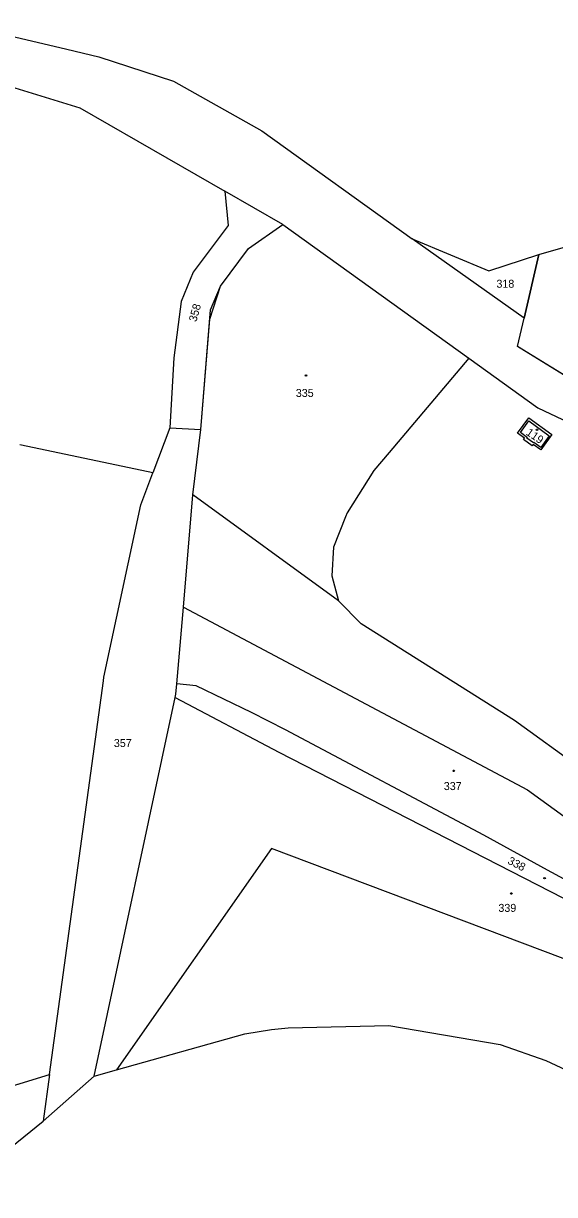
# Model space of a CAD drawing. Extents: x -841286 to -834997, y -1020681 to -1017810.
# Drawn here: x -836086.8 to -835974.1, y -1019708.5 to -1019459.7 of the extents above; entities that cross this region are included whole.
import ezdxf

# ---------------------------------------------------------------- set-up
doc = ezdxf.new("R2010")
doc.units = 0
for name, color, linetype in [('OVNE_POP', 7, 'Continuous'), ('OVNE_PRE', 7, 'Continuous'), ('OVNE_SET', 7, 'Continuous'), ('OVNI_PRE', 7, 'Continuous'), ('OVNI_SET', 7, 'Continuous')]:
    doc.layers.add(name, color=color, linetype=linetype)

msp = doc.modelspace()

# ---------------------------------------------------------------- linework, layer by layer
at = {"layer": 'OVNE_POP'}
for points in [[(-836026.74, -1019534.34), (-836026.65, -1019534.49), (-836026.74, -1019534.64), (-836026.92, -1019534.64), (-836027.01, -1019534.49), (-836026.92, -1019534.34)], [(-835995.38, -1019618.36), (-835995.29, -1019618.51), (-835995.38, -1019618.66), (-835995.56, -1019618.66), (-835995.65, -1019618.51), (-835995.56, -1019618.36)], [(-835976.04, -1019641.21), (-835976.03, -1019641.38), (-835976.18, -1019641.47), (-835976.34, -1019641.39), (-835976.35, -1019641.22), (-835976.2, -1019641.13)], [(-835983.15, -1019644.41), (-835983.06, -1019644.56), (-835983.15, -1019644.71), (-835983.33, -1019644.71), (-835983.42, -1019644.56), (-835983.33, -1019644.41)]]:
    msp.add_lwpolyline(points, close=True, dxfattribs=at)
at = {"layer": 'OVNE_SET'}
for p, q in [((-836100.7, -1019459.72), (-836077.61, -1019465.18)), ((-836077.61, -1019465.18), (-836070.81, -1019466.85)), ((-836102.74, -1019469.13), (-836074.81, -1019477.66)), ((-836070.81, -1019466.85), (-836054.99, -1019471.99)), ((-836054.99, -1019471.99), (-836036.21, -1019482.56)), ((-836074.81, -1019477.66), (-836044.05, -1019495.33)), ((-836036.21, -1019482.56), (-836004.29, -1019505.46)), ((-835977.44, -1019508.81), (-835896.74, -1019485.76)), ((-836044.05, -1019495.33), (-836043.36, -1019502.68)), ((-836031.74, -1019502.43), (-836044.05, -1019495.33)), ((-836043.36, -1019502.68), (-836050.77, -1019512.55)), ((-836039.02, -1019507.52), (-836031.74, -1019502.43)), ((-836031.74, -1019502.43), (-835992.24, -1019530.86)), ((-836004.29, -1019505.46), (-835988.02, -1019512.3)), ((-835980.55, -1019522.3), (-836004.29, -1019505.46)), ((-836044.98, -1019515.5), (-836039.02, -1019507.52)), ((-835988.02, -1019512.3), (-835977.44, -1019508.81)), ((-835977.44, -1019508.81), (-835980.55, -1019522.3)), ((-836050.77, -1019512.55), (-836053.34, -1019518.8)), ((-836047.08, -1019520.56), (-836044.98, -1019515.5)), ((-836053.34, -1019518.8), (-836054.91, -1019530.79)), ((-836049.17, -1019545.96), (-836047.08, -1019520.56)), ((-835981.95, -1019528.35), (-835980.55, -1019522.3)), ((-835964.53, -1019539.07), (-835981.95, -1019528.35)), ((-836054.91, -1019530.79), (-836055.71, -1019545.6)), ((-835992.24, -1019530.86), (-836009.2, -1019550.87)), ((-835992.24, -1019530.86), (-835977.64, -1019541.38)), ((-835977.64, -1019541.38), (-835967.33, -1019546.31)), ((-836055.71, -1019545.6), (-836059.34, -1019555.19)), ((-836055.71, -1019545.6), (-836049.17, -1019545.96)), ((-836050.88, -1019559.87), (-836049.17, -1019545.96)), ((-836069.74, -1019553), (-836087.56, -1019549.25)), ((-836009.2, -1019550.87), (-836012.43, -1019554.69)), ((-836059.34, -1019555.19), (-836069.74, -1019553)), ((-836061.92, -1019562), (-836059.34, -1019555.19)), ((-836012.43, -1019554.69), (-836018.11, -1019563.68)), ((-836052.87, -1019583.71), (-836050.88, -1019559.87)), ((-836019.93, -1019582.35), (-836050.88, -1019559.87)), ((-836069.72, -1019598.62), (-836061.92, -1019562)), ((-836018.11, -1019563.68), (-836018.44, -1019564.54)), ((-836018.44, -1019564.54), (-836020.97, -1019571.01)), ((-836020.97, -1019571.01), (-836021.37, -1019577.04)), ((-836021.37, -1019577.04), (-836019.93, -1019582.35)), ((-836054.22, -1019599.98), (-836052.87, -1019583.71)), ((-836052.87, -1019583.71), (-835979.84, -1019622.54)), ((-836015.16, -1019587.27), (-836019.93, -1019582.35)), ((-835982.57, -1019607.79), (-836015.16, -1019587.27)), ((-836069.85, -1019599.4), (-836069.72, -1019598.62)), ((-836081.27, -1019683), (-836069.85, -1019599.4)), ((-836054.46, -1019602.21), (-836054.22, -1019599.98)), ((-836050.17, -1019600.42), (-836054.22, -1019599.98)), ((-836038.41, -1019606.13), (-836050.17, -1019600.42)), ((-836071.78, -1019683.33), (-836054.58, -1019602.94)), ((-836054.58, -1019602.94), (-836054.46, -1019602.21)), ((-836054.58, -1019602.94), (-836032.59, -1019614.53)), ((-836031.18, -1019609.8), (-836038.41, -1019606.13)), ((-835968.17, -1019618.29), (-835982.57, -1019607.79)), ((-835989.09, -1019632.18), (-836031.18, -1019609.8)), ((-836032.59, -1019614.53), (-835969.54, -1019646.89)), ((-835979.84, -1019622.54), (-835903.29, -1019678.02)), ((-835975.56, -1019639.57), (-835989.09, -1019632.18)), ((-836034.19, -1019634.96), (-836067.09, -1019682.01)), ((-835937.02, -1019671.68), (-836034.19, -1019634.96)), ((-835950.97, -1019653.1), (-835975.56, -1019639.57)), ((-836034.17, -1019673.46), (-836030.61, -1019673.1)), ((-836030.61, -1019673.1), (-836009.27, -1019672.61)), ((-836009.27, -1019672.61), (-835985.65, -1019676.6)), ((-836067.09, -1019682.01), (-836039.82, -1019674.35)), ((-836039.82, -1019674.35), (-836034.17, -1019673.46)), ((-835985.65, -1019676.6), (-835975.95, -1019680.01)), ((-835975.95, -1019680.01), (-835960.3, -1019687.33)), ((-836100.96, -1019689.05), (-836081.27, -1019683)), ((-836081.27, -1019683), (-836082.63, -1019692.89)), ((-836071.78, -1019683.33), (-836067.09, -1019682.01)), ((-836082.63, -1019692.89), (-836071.78, -1019683.33)), ((-836101.96, -1019708.51), (-836082.63, -1019692.89))]:
    msp.add_line(p, q, dxfattribs=at)
msp.add_lwpolyline([(-835979.54, -1019543.53), (-835974.63, -1019547.05), (-835976.97, -1019550.33), (-835978.61, -1019549.15), (-835978.82, -1019549.46), (-835980.64, -1019548.13), (-835980.45, -1019547.83), (-835981.92, -1019546.74), (-835979.54, -1019543.53)], dxfattribs=at)
at = {"layer": 'OVNI_PRE'}
msp.add_lwpolyline([(-835977.71, -1019545.9), (-835977.62, -1019546.05), (-835977.71, -1019546.2), (-835977.89, -1019546.2), (-835977.98, -1019546.05), (-835977.89, -1019545.9)], close=True, dxfattribs=at)
at = {"layer": 'OVNI_SET'}
for points in [[(-835964.53, -1019539.07), (-835981.95, -1019528.35), (-835980.55, -1019522.3), (-835977.44, -1019508.81), (-835896.74, -1019485.7)], [(-836100.96, -1019689.05), (-836081.27, -1019683), (-836082.63, -1019692.89), (-836071.78, -1019683.33), (-836054.58, -1019602.94), (-836054.46, -1019602.21), (-836054.22, -1019599.98), (-836052.87, -1019583.71), (-836050.88, -1019559.87), (-836049.17, -1019545.96), (-836047.24, -1019522.54), (-836044.98, -1019515.5), (-836039.02, -1019507.52), (-836031.74, -1019502.43), (-836044.05, -1019495.33), (-836043.36, -1019502.68), (-836050.77, -1019512.55), (-836053.34, -1019518.8), (-836054.91, -1019530.79), (-836055.71, -1019545.6), (-836059.34, -1019555.19), (-836069.74, -1019553), (-836087.56, -1019549.25)], [(-835979.55, -1019544.17), (-835975.22, -1019547.3), (-835977.01, -1019549.8), (-835978.48, -1019548.73), (-835978.57, -1019548.85), (-835979.94, -1019547.85), (-835979.85, -1019547.73), (-835981.33, -1019546.65), (-835979.55, -1019544.17)]]:
    msp.add_lwpolyline(points, dxfattribs=at)

# ---------------------------------------------------------------- texts
at = {"layer": 'OVNE_PRE'}
for s, p in [('318', (-835986.42, -1019515.87)), ('335', (-836029, -1019539.07)), ('357', (-836067.62, -1019613.44)), ('337', (-835997.59, -1019622.58)), ('339', (-835986, -1019648.46))]:
    msp.add_text(s, height=1.7, dxfattribs=at).set_placement(p)
for s, rotation, p in [('358', 74.3126, (-836050.12, -1019523.21)), ('119', 325.4973, (-835980.28, -1019546.98)), ('338', 332.8885, (-835984.18, -1019638.14))]:
    msp.add_text(s, height=1.7, rotation=rotation, dxfattribs=at).set_placement(p)

doc.saveas('drawing.dxf')
